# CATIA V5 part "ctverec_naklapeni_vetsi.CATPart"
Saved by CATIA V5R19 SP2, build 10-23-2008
Part number: ctverec_naklapeni_vetsi
Bounding box of the stored display mesh (mm): x 0 to 270, y -75 to 75, z -75 to 75
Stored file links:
  C:\Users\Martiin\Desktop\9.semestr\Projekt-diplomka\3D model\ctverec_naklapeni_vetsi.CATPart
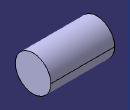
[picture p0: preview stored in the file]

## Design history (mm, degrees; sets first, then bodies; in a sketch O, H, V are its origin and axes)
Body1 (main body)
  Sketch1 on yz-plane, origin (0, 0, 0), H (0, 1, 0), V (0, 0, 1)
    circle A1 centre (0, 0) radius 75
    radius A1 = 75
  Pad1: profile Sketch1, direction (1, 0, 0), length 270
  Sketch2 on start face of Pad1, origin (0, 0, 0), H (0, -1, 0), V (0, 0, 1)
    point P1 (0, 0)
    coincidence: P1 O
  Sketch3 on start face of Pad1, origin (0, 0, 0), H (0, 1, 0), V (0, 0, -1)
    point P1 (0, 0)
    reference projected point E1 (0, 0) from Sketch2.P1
    coincidence: E1 P1
  Hole1: placed by Sketch3, at (0, 0, 0) direction (1, 0, 0), diameter 80, depth 10
  Shell1: IntOffset 10, Face face of Hole1, ExtOffset 0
